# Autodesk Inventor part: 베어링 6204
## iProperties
IsCustomPart: 0
Manager: KYOUNG IL JANG
Company: 한국ATC센터
Created: 2009-02
Part Number: 베어링 6204
Material: Steel, Mild
Description: 깊은 그루브 볼 베어링
Document SubType Name: Modeling
Standard: KS B 2023
Standards Organization: KS
Language: ko-KR
Size Designation: 6204 - 20 x 47 x 14
Categories: <MemberInstance><Categories><Category DisplayName="샤프트 부품" InternalName="7f7aeb1f-a693-4053-b835-cee3144e0d98" Mnemonic="SHFT"><Category DisplayName="베어링" Inter
Density: 1 g/cm^3
Checked By: KYOUNG IL JANG
Vendor: CBT Solutions
Designer: KYOUNG IL JANG
Author: KYOUNG IL JANG
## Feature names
1. IDS_ARRAYBALL[SIMPL:T] [Circular Pattern]
